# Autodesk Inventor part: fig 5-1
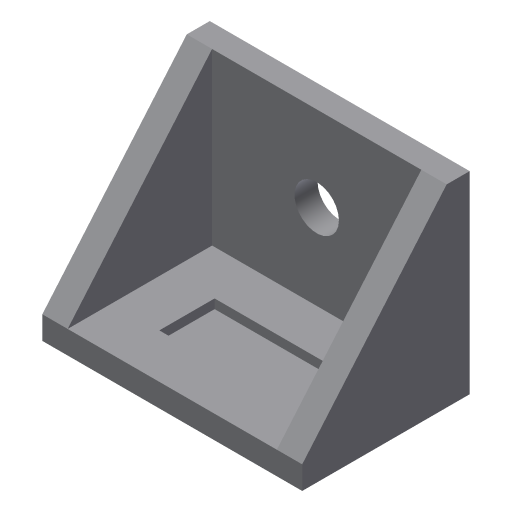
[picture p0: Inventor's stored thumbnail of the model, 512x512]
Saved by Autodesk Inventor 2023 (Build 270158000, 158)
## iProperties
Created: 2012-08
Part Number: fig 5-1
Material: Generic
Document SubType Name: Modeling
Designer: CADCIM
Density: 1 g/cm^3
Appearance: Default
Author: CADCIM
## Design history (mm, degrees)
sketch "Sketch1"
  geometry: L1 (-14.1, 7.837)-(14.1, 7.837); L2 (14.1, 7.837)-(14.1, -7.837); L3 (14.1, -7.837)-(-14.1, -7.837); L4 (-14.1, -7.837)-(-14.1, 7.837); L5 (-14.1, 7.837)-(14.1, -7.837); L6 (14.1, 7.837)-(-14.1, -7.837); 1 further point
  constraints: 12 end point, 2 midpoint, 2 parallel, 1 horizontal, 1 perpendicular
extrude "Extrusion1" new body sketch "Sketch1" distance "d0" = 2.5; taper "d1" = 0 deg
sketch "Sketch2"
  geometry: L1 (0, -20.969)-(28.201, -20.969); L2 (28.201, -20.969)-(28.201, 0); L3 (28.201, 0)-(0, 0); L4 (0, 0)-(0, -20.969); L5 (0, -20.969)-(28.201, 0); L6 (28.201, -20.969)-(0, 0); 1 further point
  constraints: 12 end point, 2 midpoint, 2 parallel, 1 horizontal, 1 perpendicular
extrude "Extrusion2" join sketch "Sketch2" distance "d2" = 2.5; taper "d3" = 0 deg
sketch "Sketch3"
  geometry: L1 (-6.24, 3)-(6.24, 3); L2 (6.24, 3)-(6.24, -3); L3 (6.24, -3)-(-6.24, -3); L4 (-6.24, -3)-(-6.24, 3); L5 (-6.24, 3)-(6.24, -3); L6 (6.24, 3)-(-6.24, -3); 1 further point
  constraints: 12 end point, 2 midpoint, 2 parallel, 1 horizontal, 1 perpendicular
extrude "Extrusion3" cut sketch "Sketch3" distance "d4" = 1; taper "d5" = 0 deg
sketch "Sketch4"
  geometry: L1 (2.5, 18.174)-(2.5, 0) reference; L2 (-18.469, 15.674)-(0, 15.674) reference; L3 (-18.469, 15.674)-(0, 0); L4 (-18.469, 15.674)-(0, 15.674); L5 (0, 0)-(0, 15.674)
  constraints: 6 end point, 1 collinear, 1 parallel
extrude "Extrusion4" join sketch "Sketch4" distance "d6" = 2.75; taper "d7" = 0 deg
mirror "Mirror1"
sketch "Sketch5"
  geometry: C1 r 2.409 at (14.1, 11.735)
  constraints: 1 centre point
extrude "Extrusion5" cut sketch "Sketch5" distance "d8" = 2.75; taper "d9" = 0 deg
body "Solid1"
